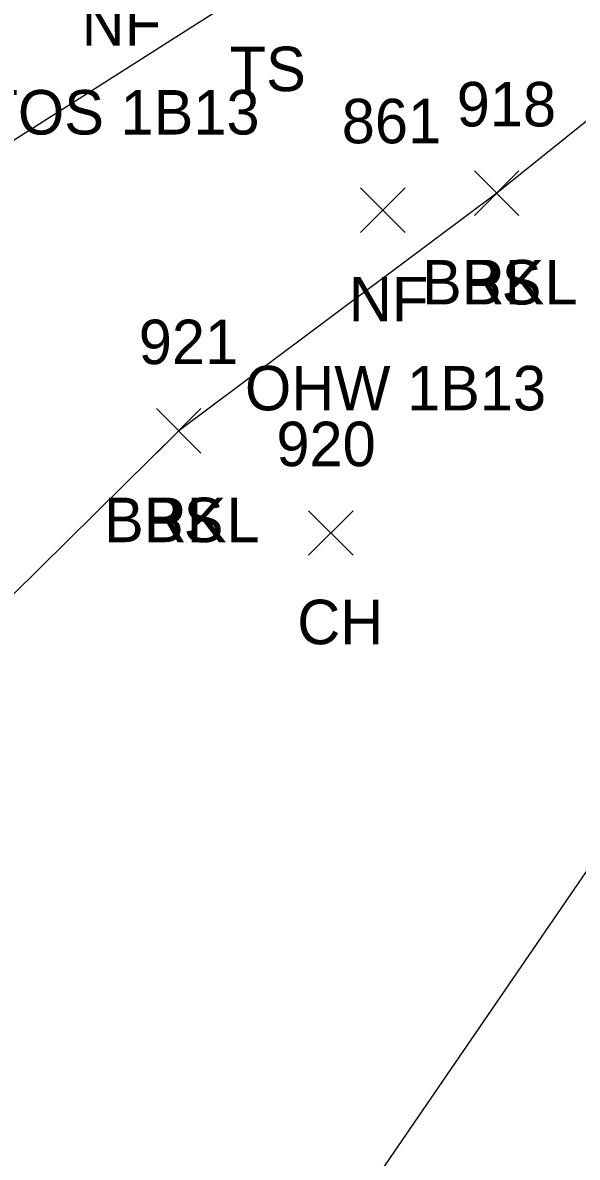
# Model space of a CAD drawing. Extents: x 1528286 to 1556263, y 492387 to 508952.
# Drawn here: x 1528516.3 to 1528541.2, y 492589.2 to 492640.2 of the extents above; entities that cross this region are included whole.
import ezdxf

# ---------------------------------------------------------------- set-up
doc = ezdxf.new("R2010")
doc.units = 0
for name, color, linetype in [('L_A', 7, 'Continuous'), ('L_C', 7, 'Continuous'), ('L_I', 7, 'Continuous'), ('L_TIC', 7, 'Continuous'), ('LAWE', 7, 'Continuous'), ('LELB', 7, 'Continuous')]:
    doc.layers.add(name, color=color, linetype=linetype)

msp = doc.modelspace()

# ---------------------------------------------------------------- linework, layer by layer
at = {"layer": 'L_TIC'}
for points in [[(1528536.626, 492631.534), (1528538.626, 492633.534)], [(1528538.626, 492631.534), (1528536.626, 492633.534)], [(1528536.626, 492631.534), (1528538.626, 492633.534)], [(1528538.626, 492631.534), (1528536.626, 492633.534)], [(1528536.626, 492631.534), (1528538.626, 492633.534)], [(1528538.626, 492631.534), (1528536.626, 492633.534)], [(1528536.626, 492631.534), (1528538.626, 492633.534)], [(1528538.626, 492631.534), (1528536.626, 492633.534)], [(1528531.509, 492630.775), (1528533.509, 492632.775)], [(1528533.509, 492630.775), (1528531.509, 492632.775)], [(1528531.509, 492630.775), (1528533.509, 492632.775)], [(1528533.509, 492630.775), (1528531.509, 492632.775)], [(1528522.345, 492620.851), (1528524.345, 492622.851)], [(1528524.345, 492620.851), (1528522.345, 492622.851)], [(1528522.345, 492620.851), (1528524.345, 492622.851)], [(1528524.345, 492620.851), (1528522.345, 492622.851)], [(1528522.345, 492620.851), (1528524.345, 492622.851)], [(1528524.345, 492620.851), (1528522.345, 492622.851)], [(1528522.345, 492620.851), (1528524.345, 492622.851)], [(1528524.345, 492620.851), (1528522.345, 492622.851)], [(1528529.179, 492616.265), (1528531.179, 492618.265)], [(1528531.179, 492616.265), (1528529.179, 492618.265)], [(1528529.179, 492616.265), (1528531.179, 492618.265)], [(1528531.179, 492616.265), (1528529.179, 492618.265)]]:
    msp.add_lwpolyline(points, dxfattribs=at)
at = {"layer": 'LAWE'}
for points in [[(1528639.893, 492735.148), (1528628.638, 492716.197), (1528619.322, 492697.772), (1528600.014, 492685.78), (1528586.494, 492675.208), (1528555.765, 492651.711), (1528552.059, 492644.142), (1528537.626, 492632.534), (1528523.345, 492621.851), (1528510.87, 492609.533), (1528497.291, 492599.489), (1528482.777, 492583.151), (1528460.774, 492562.048), (1528436.992, 492551.704), (1528418.951, 492545.204), (1528399.482, 492529.93), (1528387.952, 492519.312), (1528358.196, 492480.955)], [(1528639.893, 492735.148), (1528628.638, 492716.197), (1528619.322, 492697.772), (1528600.014, 492685.78), (1528586.494, 492675.208), (1528555.765, 492651.711), (1528552.059, 492644.142), (1528537.626, 492632.534), (1528523.345, 492621.851), (1528510.87, 492609.533), (1528497.291, 492599.489), (1528482.777, 492583.151), (1528460.774, 492562.048), (1528436.992, 492551.704), (1528418.951, 492545.204), (1528399.482, 492529.93), (1528387.952, 492519.312), (1528358.196, 492480.955)], [(1528645.438, 492730.638), (1528651.622, 492718.642), (1528645.743, 492704.772), (1528631.806, 492684.8), (1528615.475, 492671.091), (1528597.131, 492648.324), (1528570.323, 492633.929), (1528549.926, 492614.136), (1528527.115, 492580.823), (1528486.911, 492550.694), (1528466.236, 492548.442), (1528453.392, 492536.119), (1528428.919, 492520.065), (1528405.493, 492507.44), (1528391.912, 492487.091), (1528384.545, 492464.65)], [(1528645.438, 492730.638), (1528651.622, 492718.642), (1528645.743, 492704.772), (1528631.806, 492684.8), (1528615.475, 492671.091), (1528597.131, 492648.324), (1528570.323, 492633.929), (1528549.926, 492614.136), (1528527.115, 492580.823), (1528486.911, 492550.694), (1528466.236, 492548.442), (1528453.392, 492536.119), (1528428.919, 492520.065), (1528405.493, 492507.44), (1528391.912, 492487.091), (1528384.545, 492464.65)]]:
    msp.add_lwpolyline(points, dxfattribs=at)
at = {"layer": 'LELB'}
for points in [[(1528653.271, 492717.805), (1528645.743, 492704.772), (1528631.806, 492684.8), (1528615.475, 492671.091), (1528597.131, 492648.324), (1528570.323, 492633.929), (1528549.926, 492614.136), (1528527.115, 492580.823), (1528486.911, 492550.694), (1528472.867, 492532.388)], [(1528653.271, 492717.805), (1528645.743, 492704.772), (1528631.806, 492684.8), (1528615.475, 492671.091), (1528597.131, 492648.324), (1528570.323, 492633.929), (1528549.926, 492614.136), (1528527.115, 492580.823), (1528486.911, 492550.694), (1528472.867, 492532.388)], [(1528495.396, 492632.327), (1528503.178, 492626.813), (1528527.225, 492642.12), (1528549.208, 492659.483), (1528567.953, 492673.117), (1528585.347, 492688.372), (1528604.063, 492705.044), (1528609.007, 492715.026)], [(1528495.396, 492632.327), (1528503.178, 492626.813), (1528527.225, 492642.12), (1528549.208, 492659.483), (1528567.953, 492673.117), (1528585.347, 492688.372), (1528604.063, 492705.044), (1528609.007, 492715.026)], [(1528619.629, 492709.303), (1528607.886, 492695.261), (1528600.014, 492685.78), (1528586.494, 492675.208), (1528555.765, 492651.711), (1528552.059, 492644.142), (1528537.626, 492632.534), (1528523.345, 492621.851), (1528510.87, 492609.533), (1528497.291, 492599.489), (1528482.777, 492583.151), (1528460.774, 492562.048), (1528436.992, 492551.704), (1528418.951, 492545.204), (1528399.482, 492529.93), (1528387.952, 492519.312), (1528358.196, 492480.955)], [(1528619.629, 492709.303), (1528607.886, 492695.261), (1528600.014, 492685.78), (1528586.494, 492675.208), (1528555.765, 492651.711), (1528552.059, 492644.142), (1528537.626, 492632.534), (1528523.345, 492621.851), (1528510.87, 492609.533), (1528497.291, 492599.489), (1528482.777, 492583.151), (1528460.774, 492562.048), (1528436.992, 492551.704), (1528418.951, 492545.204), (1528399.482, 492529.93), (1528387.952, 492519.312), (1528358.196, 492480.955)]]:
    msp.add_lwpolyline(points, dxfattribs=at)

# ---------------------------------------------------------------- texts
at = {"layer": 'L_A'}
for s, p in [('NF', (1528518.986, 492639.17)), ('NF', (1528518.986, 492639.17)), ('TS', (1528525.635, 492637.12)), ('TS', (1528525.635, 492637.12)), ('BRKL', (1528534.271, 492627.534)), ('BRKL', (1528534.271, 492627.534)), ('BS', (1528536.067, 492627.534)), ('BS', (1528536.067, 492627.534)), ('NF', (1528530.989, 492626.775)), ('NF', (1528530.989, 492626.775)), ('BRKL', (1528519.991, 492616.851)), ('BRKL', (1528519.991, 492616.851)), ('BS', (1528521.786, 492616.851)), ('BS', (1528521.786, 492616.851)), ('CH', (1528528.668, 492612.265)), ('CH', (1528528.668, 492612.265))]:
    msp.add_text(s, height=2, dxfattribs=at).set_placement(p)
at = {"layer": 'L_C'}
for s, p in [('TOS 1B13', (1528514.49, 492635.17)), ('TOS 1B13', (1528514.49, 492635.17)), ('OHW 1B13', (1528526.32, 492622.775)), ('OHW 1B13', (1528526.32, 492622.775))]:
    msp.add_text(s, height=2, dxfattribs=at).set_placement(p)
at = {"layer": 'L_I'}
for s, p in [('918', (1528535.83, 492635.534)), ('918', (1528535.83, 492635.534)), ('918', (1528535.83, 492635.534)), ('918', (1528535.83, 492635.534)), ('861', (1528530.667, 492634.775)), ('861', (1528530.667, 492634.775)), ('921', (1528521.55, 492624.851)), ('921', (1528521.55, 492624.851)), ('921', (1528521.55, 492624.851)), ('921', (1528521.55, 492624.851)), ('920', (1528527.731, 492620.265)), ('920', (1528527.731, 492620.265))]:
    msp.add_text(s, height=2, dxfattribs=at).set_placement(p)

doc.saveas('drawing.dxf')
